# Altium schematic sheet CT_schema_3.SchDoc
size 357 x 214 mm
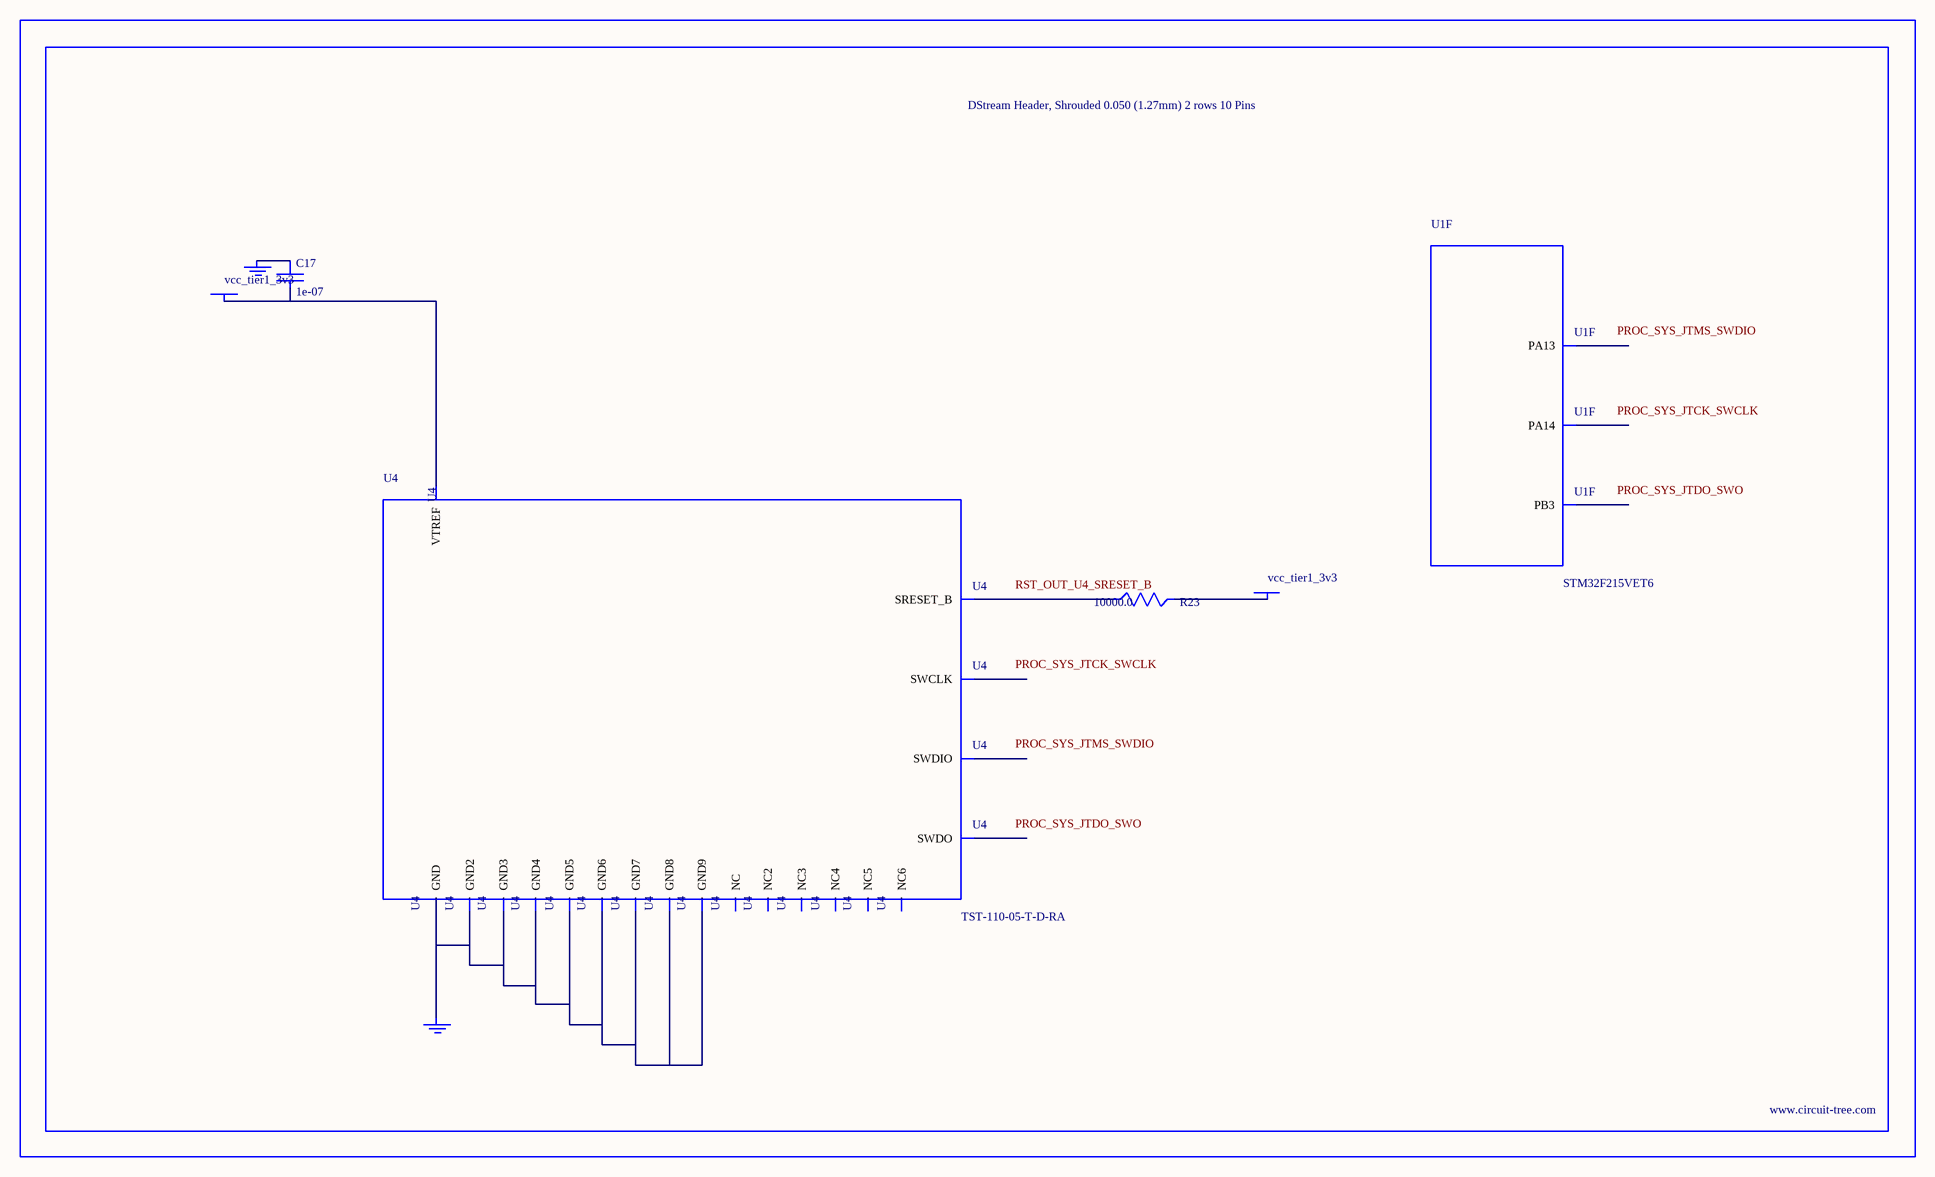
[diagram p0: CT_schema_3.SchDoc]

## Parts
BORDER2  (no value)
C17  1e-07  [C0402]
GND_INSTANCE_2_0  (no value)
GND_INSTANCE_2_1  (no value)
POWER_INSTANCE_2_0  vcc_tier1_3v3
POWER_INSTANCE_2_1  vcc_tier1_3v3
R23  10000.0  [R0603]
U1  STM32F215VET6  [LQFP100]  (part F of 9)
U4  TST-110-05-T-D-RA  [TST-110-05-T-D-RA]

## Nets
NetC17_1: C17.1 GND_INSTANCE_2_0.0(GND)
NetC17_2: C17.2 POWER_INSTANCE_2_0.0(PWR) U4.1(VTREF)
NetGND_INSTANCE_2_1_0: GND_INSTANCE_2_1.0(GND) U4.4(GND) U4.6(GND2) U4.8(GND3) U4.10(GND4) U4.12(GND5) U4.14(GND6) U4.16(GND7) U4.18(GND8) U4.20(GND9)
NetPOWER_INSTANCE_2_1_0: POWER_INSTANCE_2_1.0(PWR) R23.2
NetR23_1: R23.1 U4.15(SRESET_B)

Not connected (* = marked no-connect by the designer): U1 72(PA13) 76(PA14) 89(PB3); U4 2(NC) 3(NC2) 5(NC3) 7(SWDIO) 9(SWCLK) 11(NC4) 13(SWDO) 17(NC5) 19(NC6)

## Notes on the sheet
- Labels drawn without touching a wire or pin: PROC_SYS_JTCK_SWCLK, PROC_SYS_JTDO_SWO, PROC_SYS_JTMS_SWDIO, RST_OUT_U4_SRESET_B

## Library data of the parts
BORDER2 = BORDER_PAGE2
C17 = C0402C104K3RACTU
GND_INSTANCE_2_0 GND_INSTANCE_2_1 = GND
POWER_INSTANCE_2_0 POWER_INSTANCE_2_1 = PWR
R23 = RC0603JR-0710KL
